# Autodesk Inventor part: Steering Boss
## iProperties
Shininess: 100.0
Angle Display Precision: 2
Document Length Units: 11269
Document Angle Units: 11279
Document Time Units: 11290
Document Mass Units: 11283
Document Length Units Precision: 3
Document Angle Units Precision: 2
Compacted: True
Created: 2001-08
Part Number: Steering Boss
Document SubType Name: Modeling
Designer: Martin Budgell
Density: 0.0
Volumn: 0.0
Area: 0.0
PropertySet Name: Model Information
Control State: 0
Master: False
Checked Out: False
Author: Martin Budgell
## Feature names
1. Extrusion1
2. Extrusion2
3. Fillet1
4. Hole1
5. Chamfer1
6. Hole2
